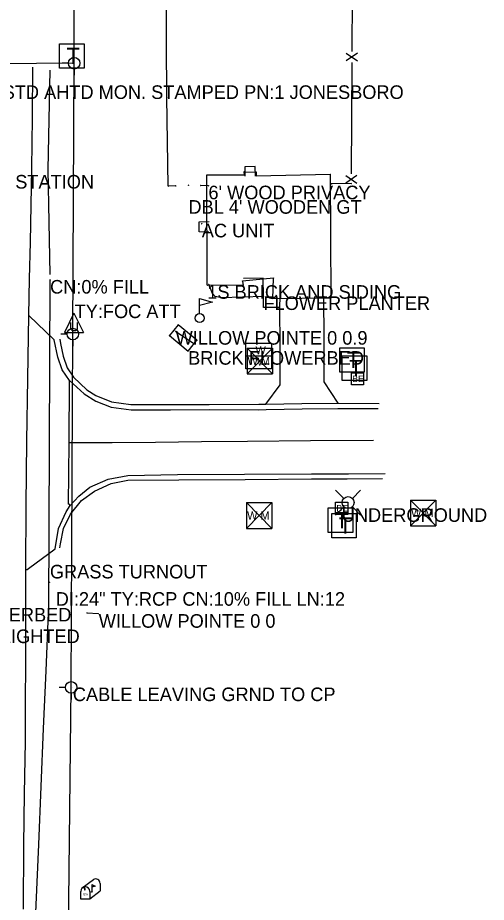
# Model space of a CAD drawing. Extents: x 1707085 to 1720058, y 548761 to 560063.
# Drawn here: x 1712493.1 to 1712665.4, y 550824.4 to 551149.9 of the extents above; entities that cross this region are included whole.
import ezdxf

# ---------------------------------------------------------------- set-up
doc = ezdxf.new("R2010")
doc.units = 0
for name, color, linetype in [('3', 7, 'Continuous'), ('R_Contours', 7, 'Continuous'), ('R_Horz Alg Annot', 7, 'Continuous'), ('R_Water Annot', 7, 'Continuous'), ('S_BUILDING', 7, 'Continuous'), ('S_BUILDING_ANNOT', 7, 'Continuous'), ('S_CURB', 7, 'Continuous'), ('S_DRG_PT_SYM', 7, 'Continuous'), ('S_DRIVEWAY', 7, 'Continuous'), ('S_EDGE_CONCRETE', 7, 'Continuous'), ('S_EDGE_PAVEMENT', 7, 'Continuous'), ('S_ELECTRIC_UTILITIES', 7, 'Continuous'), ('S_ELECTRIC_UTILITIES_ANNOT', 7, 'Continuous'), ('S_FENCE_ANNOT', 7, 'Continuous'), ('S_FLAG_POLE', 7, 'Continuous'), ('S_GATE_ANNOT', 7, 'Continuous'), ('S_MAILBOX', 7, 'Continuous'), ('S_MISC_STRUCTURES', 7, 'Continuous'), ('S_MISC_STRUCTURES_ANNOT', 7, 'Continuous'), ('S_MSC_PT_SYM', 7, 'Continuous'), ('S_PAVEMENT_CROWN', 7, 'Continuous'), ('S_PRIMARY_CTL_ANNOT', 7, 'Continuous'), ('S_SIDE_DRAIN_ANNOT', 7, 'Continuous'), ('S_SIDEWALK', 7, 'Continuous'), ('S_SIGN_ANNOT', 7, 'Continuous'), ('S_STR_PT_SYM', 7, 'Continuous'), ('S_SURVEY_TEXT_ANNOT', 7, 'Continuous'), ('S_TELEPHONE_UTILITIES', 7, 'Continuous'), ('S_UNDERGROUND_CABLE', 7, 'Continuous'), ('S_UTILITY_POLE', 7, 'Continuous'), ('S_UTILITY_POLE_ANNOT', 7, 'Continuous')]:
    doc.layers.add(name, color=color, linetype=linetype)

msp = doc.modelspace()

# ---------------------------------------------------------------- linework, layer by layer
for points in [[(1712504.99, 551055.41), (1712504.65, 551074.69), (1712504.31, 551093.97), (1712504.65, 551112.3), (1712504.99, 551130.62)], [(1712498.93, 550801.18), (1712499.86, 550823.46), (1712500.8, 550845.74), (1712501.7, 550867.04), (1712502.61, 550888.35), (1712503.52, 550909.65), (1712504.42, 550930.96)]]:
    msp.add_lwpolyline(points)
at = {"layer": '3'}
msp.add_line((1712504.5, 550932.27), (1712505, 551053.38), dxfattribs=at)
at = {"layer": 'R_Contours'}
for p, q in [((1712618.03, 551136.82), (1712613.92, 551133.97)), ((1712613.94, 551136.83), (1712618.02, 551133.95)), ((1712617.83, 551091.82), (1712613.72, 551088.97)), ((1712613.73, 551091.84), (1712617.81, 551088.95)), ((1712563.24, 551088.08), (1712560.43, 551088.11)), ((1712615.76, 551088.93), (1712608.46, 551088.73)), ((1712551.2, 551087.98), (1712548.44, 551087.93))]:
    msp.add_line(p, q, dxfattribs=at)
for points in [[(1712547.8, 551140.62), (1712547.82, 551157.97)], [(1712616.08, 551157.89), (1712615.99, 551137.44)], [(1712547.92, 551120.61), (1712547.8, 551140.62)], [(1712615.97, 551133.35), (1712615.78, 551092.44)], [(1712548.44, 551087.93), (1712547.92, 551120.61)], [(1712563.24, 551088.08), (1712560.43, 551088.11)], [(1712615.76, 551088.93), (1712608.46, 551088.73)], [(1712551.2, 551087.98), (1712548.44, 551087.93)]]:
    msp.add_lwpolyline(points, dxfattribs=at)
at = {"layer": 'R_Horz Alg Annot'}
for p, q in [((1712551.16, 551034.59), (1712557.45, 551030.23)), ((1712518.61, 550930.88), (1712522.74, 550930.71))]:
    msp.add_line(p, q, dxfattribs=at)
at = {"layer": 'R_Water Annot'}
for p, q in [((1712577, 551030.14), (1712586.42, 551030.14)), ((1712577, 551020.73), (1712577, 551030.14)), ((1712586.42, 551030.14), (1712586.42, 551020.73)), ((1712577.43, 551028.31), (1712586.77, 551028.31)), ((1712577.43, 551028.31), (1712577.43, 551018.82)), ((1712577.43, 551028.31), (1712586.77, 551018.82)), ((1712586.77, 551028.31), (1712577.43, 551018.82)), ((1712586.77, 551028.31), (1712586.77, 551018.82)), ((1712577, 551025.45), (1712586.42, 551025.45)), ((1712586.42, 551020.73), (1712577, 551020.73)), ((1712577.43, 551018.82), (1712586.77, 551018.82)), ((1712577.26, 550971.48), (1712586.6, 550971.48)), ((1712577.26, 550971.48), (1712577.26, 550961.99)), ((1712577.26, 550971.48), (1712586.6, 550961.99)), ((1712586.6, 550971.48), (1712577.26, 550961.99)), ((1712586.6, 550971.48), (1712586.6, 550961.99)), ((1712637.56, 550972.44), (1712646.9, 550972.44)), ((1712637.56, 550972.44), (1712637.56, 550962.95)), ((1712637.56, 550972.44), (1712646.9, 550962.95)), ((1712646.9, 550972.44), (1712637.56, 550962.95)), ((1712646.9, 550972.44), (1712646.9, 550962.95)), ((1712577.26, 550961.99), (1712586.6, 550961.99)), ((1712637.56, 550962.95), (1712646.9, 550962.95))]:
    msp.add_line(p, q, dxfattribs=at)
at = {"layer": 'S_BUILDING'}
for p, q in [((1712562.66, 551092.03), (1712576.47, 551092.08)), ((1712562.81, 551051.48), (1712562.66, 551092.03)), ((1712576.47, 551092.08), (1712576.36, 551093.15)), ((1712576.36, 551093.15), (1712580.78, 551093.1)), ((1712580.78, 551093.1), (1712580.79, 551091.76)), ((1712580.79, 551091.76), (1712608.03, 551092.31)), ((1712608.03, 551092.31), (1712608.25, 551046.71)), ((1712587.18, 551054.1), (1712575.82, 551052.99)), ((1712575.82, 551052.99), (1712576.02, 551051.38)), ((1712586.92, 551046.51), (1712587.18, 551054.1)), ((1712576.02, 551051.38), (1712562.81, 551051.48)), ((1712608.25, 551046.71), (1712586.92, 551046.51))]:
    msp.add_line(p, q, dxfattribs=at)
at = {"layer": 'S_CURB'}
for points in [[(1712508.53, 551031.58), (1712508.78, 551030.03), (1712509.79, 551025.42), (1712511.28, 551021.07), (1712513.66, 551017.64), (1712518.54, 551012.97), (1712521.81, 551010.85), (1712527.62, 551008.55), (1712534.69, 551007.53), (1712549.11, 551007.53), (1712563.52, 551007.52), (1712581.8, 551007.74), (1712584.38, 551007.76), (1712597.6, 551007.91), (1712610.82, 551008.05), (1712625.99, 551007.95)], [(1712508.59, 550954.87), (1712508.82, 550956.34), (1712509.94, 550961.92), (1712512.48, 550967.27), (1712516.5, 550972.32), (1712521.28, 550975.66), (1712527.45, 550978.57), (1712533.63, 550979.74), (1712552.4, 550979.84), (1712576.79, 550980.03), (1712601.19, 550980.22), (1712614.22, 550980.29), (1712627.25, 550980.35)]]:
    msp.add_lwpolyline(points, dxfattribs=at)
at = {"layer": 'S_DRG_PT_SYM'}
for points in [[(1712505, 551053.38), (1712505, 551053.43), (1712505, 551053.38), (1712504.95, 551053.38), (1712505, 551053.38), (1712505, 551053.33), (1712505, 551053.38), (1712505.05, 551053.38)], [(1712504.5, 550932.27), (1712504.5, 550932.32), (1712504.5, 550932.27), (1712504.45, 550932.27), (1712504.5, 550932.27), (1712504.5, 550932.22), (1712504.5, 550932.27), (1712504.55, 550932.27)]]:
    msp.add_lwpolyline(points, dxfattribs=at)
at = {"layer": 'S_DRIVEWAY'}
for points in [[(1712584.38, 551007.76), (1712589.64, 551014.78), (1712589.57, 551029.04), (1712589.5, 551043.3), (1712589.68, 551047.28)], [(1712605.56, 551047.42), (1712605.64, 551031.65), (1712605.73, 551015.88), (1712610.82, 551008.05)]]:
    msp.add_lwpolyline(points, dxfattribs=at)
at = {"layer": 'S_EDGE_CONCRETE'}
for points in [[(1712580.59, 551091.6), (1712580.48, 551095.15), (1712576.65, 551095.07), (1712576.68, 551091.61)], [(1712563.43, 551071), (1712559.79, 551071.16), (1712559.77, 551074.77), (1712563.47, 551074.85)], [(1712496.11, 550946.87), (1712496.59, 550946.88), (1712497, 550947.29), (1712506.81, 550954.45), (1712508.12, 550961.97), (1712510.89, 550968.09), (1712512.39, 550970.38), (1712512.06, 550970.86), (1712511.74, 550970.86), (1712511.96, 550993.46), (1712512.19, 551016.36), (1712509.5, 551020.39), (1712507.88, 551024.95), (1712506.56, 551031.37), (1712497.17, 551040.29)]]:
    msp.add_lwpolyline(points, dxfattribs=at)
at = {"layer": 'S_EDGE_PAVEMENT'}
for points in [[(1712495.22, 550821.87), (1712495.32, 550845.5), (1712495.61, 550864.5), (1712495.9, 550883.5), (1712495.97, 550897.95), (1712496.05, 550912.4), (1712496.08, 550929.64), (1712496.11, 550946.87), (1712496.25, 550970.48), (1712496.4, 550994.08), (1712496.78, 551017.19), (1712497.17, 551040.29), (1712497.46, 551053.82), (1712497.74, 551067.34), (1712498.02, 551080.87), (1712498.31, 551094.4), (1712498.48, 551113.06), (1712498.65, 551131.73)], [(1712512.19, 551016.36), (1712517.57, 551011.46), (1712521.81, 551008.85), (1712527.45, 551006.63), (1712534.78, 551005.59), (1712549.27, 551005.67), (1712563.76, 551005.74), (1712581.66, 551005.67), (1712584.49, 551005.79), (1712597.65, 551005.95), (1712610.82, 551006.1), (1712625.61, 551006.09)], [(1712512.39, 550970.38), (1712515.63, 550973.88), (1712519.67, 550977.13), (1712526.39, 550980.12), (1712533.55, 550981.46), (1712551.87, 550981.8), (1712576.52, 550981.93), (1712601.16, 550982.06), (1712614.69, 550982.13), (1712628.23, 550982.2)]]:
    msp.add_lwpolyline(points, dxfattribs=at)
at = {"layer": 'S_ELECTRIC_UTILITIES'}
for points in [[(1712615.82, 551014.78), (1712615.82, 551019.28), (1712620.32, 551019.28), (1712620.32, 551014.78)], [(1712609.99, 550967.15), (1712609.99, 550971.65), (1712614.49, 550971.65), (1712614.49, 550967.15)]]:
    msp.add_lwpolyline(points, close=True, dxfattribs=at)
at = {"layer": 'S_FLAG_POLE'}
for p, q in [((1712560, 551041), (1712560, 551046.54)), ((1712560, 551046.54), (1712564.77, 551045.26)), ((1712564.77, 551045.26), (1712560, 551043.98))]:
    msp.add_line(p, q, dxfattribs=at)
msp.add_circle((1712560, 551039.37), 1.63, dxfattribs=at)
at = {"layer": 'S_MAILBOX'}
for p, q in [((1712516.8, 550829.75), (1712520.93, 550832.86)), ((1712520.41, 550831.04), (1712520.41, 550828.33)), ((1712523.36, 550831.39), (1712523.36, 550828.67)), ((1712516.24, 550828.48), (1712516.24, 550825.76)), ((1712519.57, 550825.76), (1712523.36, 550828.67)), ((1712519.57, 550828.48), (1712519.57, 550825.76)), ((1712516.24, 550825.76), (1712519.57, 550825.76))]:
    msp.add_line(p, q, dxfattribs=at)
for points in [[(1712520.41, 550831.04), (1712521.52, 550830.38), (1712520.41, 550830.03)], [(1712517.43, 550829.59), (1712517.65, 550829.45), (1712517.65, 550829.07), (1712517.95, 550829.07), (1712517.95, 550829.43), (1712517.76, 550829.68), (1712517.43, 550829.62)]]:
    msp.add_lwpolyline(points, dxfattribs=at)
for centre, end in [((1712521.7, 550831.39), 117.5718), ((1712517.91, 550828.48), 180)]:
    msp.add_arc(centre, 1.66, 0, end, dxfattribs=at)
msp.add_ellipse((1712520.41, 550828.33), major_axis=(0.145, 0.132), ratio=0.564646, dxfattribs=at)
at = {"layer": 'S_MISC_STRUCTURES'}
for p, q in [((1712564.74, 551048.38), (1712563.37, 551051.67)), ((1712565.69, 551047.28), (1712564.74, 551048.38)), ((1712568.1, 551046.85), (1712565.69, 551047.28)), ((1712583.47, 551047.35), (1712568.1, 551046.85)), ((1712552.13, 551036.94), (1712548.88, 551033.01)), ((1712559.01, 551031.22), (1712552.13, 551036.94)), ((1712548.88, 551033.01), (1712555.78, 551027.22)), ((1712555.78, 551027.22), (1712559.01, 551031.22))]:
    msp.add_line(p, q, dxfattribs=at)
at = {"layer": 'S_MSC_PT_SYM'}
for points in [[(1712547.8, 551140.62), (1712547.8, 551140.67), (1712547.8, 551140.62), (1712547.75, 551140.62), (1712547.8, 551140.62), (1712547.8, 551140.57), (1712547.8, 551140.62), (1712547.85, 551140.62)], [(1712547.92, 551120.61), (1712547.92, 551120.66), (1712547.92, 551120.61), (1712547.87, 551120.61), (1712547.92, 551120.61), (1712547.92, 551120.56), (1712547.92, 551120.61), (1712547.97, 551120.61)], [(1712548.44, 551087.93), (1712548.44, 551087.98), (1712548.44, 551087.93), (1712548.39, 551087.93), (1712548.44, 551087.93), (1712548.44, 551087.88), (1712548.44, 551087.93), (1712548.49, 551087.93)], [(1712551.2, 551087.98), (1712551.2, 551088.03), (1712551.2, 551087.98), (1712551.15, 551087.98), (1712551.2, 551087.98), (1712551.2, 551087.93), (1712551.2, 551087.98), (1712551.25, 551087.98)], [(1712555.88, 551088.24), (1712555.88, 551088.29), (1712555.88, 551088.24), (1712555.83, 551088.24), (1712555.88, 551088.24), (1712555.88, 551088.19), (1712555.88, 551088.24), (1712555.93, 551088.24)], [(1712560.43, 551088.11), (1712560.43, 551088.16), (1712560.43, 551088.11), (1712560.38, 551088.11), (1712560.43, 551088.11), (1712560.43, 551088.06), (1712560.43, 551088.11), (1712560.48, 551088.11)], [(1712563.24, 551088.08), (1712563.24, 551088.13), (1712563.24, 551088.08), (1712563.19, 551088.08), (1712563.24, 551088.08), (1712563.24, 551088.03), (1712563.24, 551088.08), (1712563.29, 551088.08)], [(1712608.46, 551088.73), (1712608.46, 551088.78), (1712608.46, 551088.73), (1712608.41, 551088.73), (1712608.46, 551088.73), (1712608.46, 551088.68), (1712608.46, 551088.73), (1712608.51, 551088.73)], [(1712615.76, 551088.93), (1712615.76, 551088.98), (1712615.76, 551088.93), (1712615.71, 551088.93), (1712615.76, 551088.93), (1712615.76, 551088.88), (1712615.76, 551088.93), (1712615.81, 551088.93)], [(1712560.79, 551074.07), (1712560.79, 551074.12), (1712560.79, 551074.07), (1712560.74, 551074.07), (1712560.79, 551074.07), (1712560.79, 551074.02), (1712560.79, 551074.07), (1712560.84, 551074.07)], [(1712563.37, 551051.67), (1712563.37, 551051.72), (1712563.37, 551051.67), (1712563.32, 551051.67), (1712563.37, 551051.67), (1712563.37, 551051.62), (1712563.37, 551051.67), (1712563.42, 551051.67)], [(1712564.74, 551048.38), (1712564.74, 551048.43), (1712564.74, 551048.38), (1712564.69, 551048.38), (1712564.74, 551048.38), (1712564.74, 551048.33), (1712564.74, 551048.38), (1712564.79, 551048.38)], [(1712565.69, 551047.28), (1712565.69, 551047.33), (1712565.69, 551047.28), (1712565.64, 551047.28), (1712565.69, 551047.28), (1712565.69, 551047.23), (1712565.69, 551047.28), (1712565.74, 551047.28)], [(1712568.1, 551046.85), (1712568.1, 551046.9), (1712568.1, 551046.85), (1712568.05, 551046.85), (1712568.1, 551046.85), (1712568.1, 551046.8), (1712568.1, 551046.85), (1712568.15, 551046.85)], [(1712583.47, 551047.35), (1712583.47, 551047.4), (1712583.47, 551047.35), (1712583.42, 551047.35), (1712583.47, 551047.35), (1712583.47, 551047.3), (1712583.47, 551047.35), (1712583.52, 551047.35)], [(1712552.13, 551036.94), (1712552.13, 551036.99), (1712552.13, 551036.94), (1712552.08, 551036.94), (1712552.13, 551036.94), (1712552.13, 551036.89), (1712552.13, 551036.94), (1712552.18, 551036.94)], [(1712548.88, 551033.01), (1712548.88, 551033.06), (1712548.88, 551033.01), (1712548.83, 551033.01), (1712548.88, 551033.01), (1712548.88, 551032.96), (1712548.88, 551033.01), (1712548.93, 551033.01)], [(1712551.16, 551034.59), (1712551.16, 551034.64), (1712551.16, 551034.59), (1712551.11, 551034.59), (1712551.16, 551034.59), (1712551.16, 551034.54), (1712551.16, 551034.59), (1712551.21, 551034.59)], [(1712557.45, 551030.23), (1712557.45, 551030.28), (1712557.45, 551030.23), (1712557.4, 551030.23), (1712557.45, 551030.23), (1712557.45, 551030.18), (1712557.45, 551030.23), (1712557.5, 551030.23)], [(1712559.01, 551031.22), (1712559.01, 551031.27), (1712559.01, 551031.22), (1712558.96, 551031.22), (1712559.01, 551031.22), (1712559.01, 551031.17), (1712559.01, 551031.22), (1712559.06, 551031.22)], [(1712555.78, 551027.22), (1712555.78, 551027.27), (1712555.78, 551027.22), (1712555.73, 551027.22), (1712555.78, 551027.22), (1712555.78, 551027.17), (1712555.78, 551027.22), (1712555.83, 551027.22)], [(1712504.73, 550942.18), (1712504.73, 550942.23), (1712504.73, 550942.18), (1712504.68, 550942.18), (1712504.73, 550942.18), (1712504.73, 550942.13), (1712504.73, 550942.18), (1712504.78, 550942.18)], [(1712518.61, 550930.88), (1712518.61, 550930.93), (1712518.61, 550930.88), (1712518.56, 550930.88), (1712518.61, 550930.88), (1712518.61, 550930.83), (1712518.61, 550930.88), (1712518.66, 550930.88)], [(1712522.74, 550930.71), (1712522.74, 550930.76), (1712522.74, 550930.71), (1712522.69, 550930.71), (1712522.74, 550930.71), (1712522.74, 550930.66), (1712522.74, 550930.71), (1712522.79, 550930.71)], [(1712513.37, 550903.46), (1712513.37, 550903.51), (1712513.37, 550903.46), (1712513.32, 550903.46), (1712513.37, 550903.46), (1712513.37, 550903.41), (1712513.37, 550903.46), (1712513.42, 550903.46)]]:
    msp.add_lwpolyline(points, dxfattribs=at)
at = {"layer": 'S_PAVEMENT_CROWN'}
msp.add_lwpolyline([(1712623.93, 550994.3), (1712600.74, 550994.16), (1712577.55, 550994.02), (1712560.66, 550993.8), (1712543.77, 550993.59), (1712527.87, 550993.52), (1712511.96, 550993.46)], dxfattribs=at)
at = {"layer": 'S_SIDEWALK'}
msp.add_lwpolyline([(1712589.5, 551043.3), (1712583.45, 551043.28), (1712583.47, 551047.35), (1712583.41, 551054.03), (1712576.11, 551053.95)], dxfattribs=at)
at = {"layer": 'S_STR_PT_SYM'}
for points in [[(1712562.66, 551092.03), (1712562.66, 551092.08), (1712562.66, 551092.03), (1712562.61, 551092.03), (1712562.66, 551092.03), (1712562.66, 551091.98), (1712562.66, 551092.03), (1712562.71, 551092.03)], [(1712576.36, 551093.15), (1712576.36, 551093.2), (1712576.36, 551093.15), (1712576.31, 551093.15), (1712576.36, 551093.15), (1712576.36, 551093.1), (1712576.36, 551093.15), (1712576.41, 551093.15)], [(1712576.47, 551092.08), (1712576.47, 551092.13), (1712576.47, 551092.08), (1712576.42, 551092.08), (1712576.47, 551092.08), (1712576.47, 551092.03), (1712576.47, 551092.08), (1712576.52, 551092.08)], [(1712580.78, 551093.1), (1712580.78, 551093.15), (1712580.78, 551093.1), (1712580.73, 551093.1), (1712580.78, 551093.1), (1712580.78, 551093.05), (1712580.78, 551093.1), (1712580.83, 551093.1)], [(1712580.79, 551091.76), (1712580.79, 551091.81), (1712580.79, 551091.76), (1712580.74, 551091.76), (1712580.79, 551091.76), (1712580.79, 551091.71), (1712580.79, 551091.76), (1712580.84, 551091.76)], [(1712608.03, 551092.31), (1712608.03, 551092.36), (1712608.03, 551092.31), (1712607.98, 551092.31), (1712608.03, 551092.31), (1712608.03, 551092.26), (1712608.03, 551092.31), (1712608.08, 551092.31)], [(1712575.82, 551052.99), (1712575.82, 551053.04), (1712575.82, 551052.99), (1712575.77, 551052.99), (1712575.82, 551052.99), (1712575.82, 551052.94), (1712575.82, 551052.99), (1712575.87, 551052.99)], [(1712587.18, 551054.1), (1712587.18, 551054.15), (1712587.18, 551054.1), (1712587.13, 551054.1), (1712587.18, 551054.1), (1712587.18, 551054.05), (1712587.18, 551054.1), (1712587.23, 551054.1)], [(1712562.81, 551051.48), (1712562.81, 551051.53), (1712562.81, 551051.48), (1712562.76, 551051.48), (1712562.81, 551051.48), (1712562.81, 551051.43), (1712562.81, 551051.48), (1712562.86, 551051.48)], [(1712576.02, 551051.38), (1712576.02, 551051.43), (1712576.02, 551051.38), (1712575.97, 551051.38), (1712576.02, 551051.38), (1712576.02, 551051.33), (1712576.02, 551051.38), (1712576.07, 551051.38)], [(1712586.92, 551046.51), (1712586.92, 551046.56), (1712586.92, 551046.51), (1712586.87, 551046.51), (1712586.92, 551046.51), (1712586.92, 551046.46), (1712586.92, 551046.51), (1712586.97, 551046.51)], [(1712608.25, 551046.71), (1712608.25, 551046.76), (1712608.25, 551046.71), (1712608.2, 551046.71), (1712608.25, 551046.71), (1712608.25, 551046.66), (1712608.25, 551046.71), (1712608.3, 551046.71)]]:
    msp.add_lwpolyline(points, dxfattribs=at)
at = {"layer": 'S_TELEPHONE_UTILITIES'}
for points in [[(1712508.51, 551131.3), (1712508.51, 551140.3), (1712517.51, 551140.3), (1712517.51, 551131.3)], [(1712611.56, 551019.46), (1712611.56, 551028.46), (1712620.56, 551028.46), (1712620.56, 551019.46)], [(1712612.48, 551016.45), (1712612.48, 551025.45), (1712621.48, 551025.45), (1712621.48, 551016.45)], [(1712607.3, 550960.52), (1712607.3, 550969.52), (1712616.3, 550969.52), (1712616.3, 550960.52)], [(1712608.6, 550958.52), (1712608.6, 550967.52), (1712617.6, 550967.52), (1712617.6, 550958.52)]]:
    msp.add_lwpolyline(points, close=True, dxfattribs=at)
at = {"layer": 'S_UNDERGROUND_CABLE'}
for p, q in [((1712513.77, 551041.2), (1712510.25, 551034.11)), ((1712513.77, 551041.2), (1712517.26, 551034.11)), ((1712512.57, 551035.35), (1712512.57, 551037.79)), ((1712514.94, 551037.79), (1712514.94, 551035.35)), ((1712510.25, 551034.11), (1712517.26, 551034.11)), ((1712513.19, 551034.69), (1712512.57, 551035.35)), ((1712514.39, 551034.69), (1712513.19, 551034.69)), ((1712514.94, 551035.35), (1712514.39, 551034.69))]:
    msp.add_line(p, q, dxfattribs=at)
at = {"layer": 'S_UTILITY_POLE'}
for p, q in [((1712513.87, 551133.13), (1712513.87, 551316)), ((1712513.87, 551135.24), (1712513.87, 551137.48)), ((1712511.78, 551133.11), (1712509.45, 551133.11)), ((1712513.95, 551128.69), (1712513.95, 551131.01)), ((1712513.37, 551035.6), (1712513.37, 551037.84)), ((1712511.28, 551033.46), (1712508.95, 551033.46)), ((1712513.45, 551029.05), (1712513.45, 551031.37)), ((1712613.01, 550973.06), (1712610.03, 550976.05)), ((1712616.19, 550973.06), (1712619.17, 550976.05)), ((1712613.01, 550969.88), (1712610.03, 550966.9)), ((1712616.19, 550969.88), (1712619.17, 550966.9)), ((1712512.75, 550905.64), (1712512.75, 550907.88)), ((1712510.66, 550903.5), (1712508.34, 550903.5)), ((1712512.83, 550899.09), (1712512.83, 550901.41))]:
    msp.add_line(p, q, dxfattribs=at)
msp.add_lwpolyline([(1712497.7, 549518.48), (1712500.91, 549949.57), (1712500.58, 550149.34), (1712502.49, 550416.34), (1712509.79, 550634.49), (1712512.76, 550903.53), (1712513.37, 551033.49), (1712513.87, 551133.13), (1712444.45, 551132.54)], dxfattribs=at)
for centre, radius in [((1712513.87, 551133.13), 2.13), ((1712513.37, 551033.49), 2.13), ((1712614.61, 550971.48), 2.21), ((1712512.76, 550903.53), 2.13)]:
    msp.add_circle(centre, radius, dxfattribs=at)

# ---------------------------------------------------------------- texts
at = {"layer": 'R_Water Annot'}
for s, p in [('W', (1712580.55, 551025.98)), ('W M', (1712577.64, 551022.08)), ('V', (1712580.79, 551021.92)), ('W M', (1712577.47, 550965.25)), ('W M', (1712637.76, 550966.21))]:
    msp.add_text(s, height=3, rotation=360, dxfattribs=at).set_placement(p)
at = {"layer": 'S_BUILDING_ANNOT'}
msp.add_text('1S BRICK AND SIDING', height=5, dxfattribs=at).set_placement((1712562.81, 551046.48))
at = {"layer": 'S_ELECTRIC_UTILITIES'}
for p in [(1712616.14, 551015.83), (1712610.31, 550968.2)]:
    msp.add_text('BE', height=2.4, rotation=360, dxfattribs=at).set_placement(p)
at = {"layer": 'S_ELECTRIC_UTILITIES_ANNOT'}
msp.add_text('UNDERGROUND', height=5, dxfattribs=at).set_placement((1712612.26, 550964.4))
at = {"layer": 'S_FENCE_ANNOT'}
msp.add_text("6' WOOD PRIVACY", height=5, dxfattribs=at).set_placement((1712563.24, 551083.08))
at = {"layer": 'S_GATE_ANNOT'}
msp.add_text("DBL 4' WOODEN GT", height=5, dxfattribs=at).set_placement((1712555.88, 551077.76))
at = {"layer": 'S_MAILBOX'}
msp.add_text('US', height=0.96, rotation=360, dxfattribs=at).set_placement((1712517.01, 550826.96))
at = {"layer": 'S_MISC_STRUCTURES_ANNOT'}
for s, p in [('GAS TEST STATION', (1712457.27, 551087.02)), ('AC UNIT', (1712560.79, 551069.07)), ('FLOWER PLANTER', (1712583.47, 551042.35)), ('BRICK FLOWERBED', (1712555.78, 551022.22)), ("3.6'X3.6' BRICK FLOWERBED", (1712420.74, 550927.76))]:
    msp.add_text(s, height=5, dxfattribs=at).set_placement(p)
at = {"layer": 'S_PRIMARY_CTL_ANNOT'}
msp.add_text('PD:STD AHTD MON. STAMPED PN:1 JONESBORO', height=5, dxfattribs=at).set_placement((1712476.42, 551119.99))
at = {"layer": 'S_SIDE_DRAIN_ANNOT'}
for s, p in [('CN:0% FILL', (1712505, 551048.38)), ('DI:24" TY:RCP CN:10% FILL LN:12', (1712507.06, 550933.55))]:
    msp.add_text(s, height=5, dxfattribs=at).set_placement(p)
at = {"layer": 'S_SIGN_ANNOT'}
for s, p in [('WILLOW POINTE 0 0.9', (1712551.16, 551029.59)), ('WILLOW POINTE 0 0', (1712522.88, 550925.45)), ("CHANGEABLE 0 4' TY:PLST,MTL,LIGHTED", (1712382.73, 550919.81))]:
    msp.add_text(s, height=5, dxfattribs=at).set_placement(p)
at = {"layer": 'S_SURVEY_TEXT_ANNOT'}
for s, p in [('GRASS TURNOUT', (1712504.94, 550943.59)), ('CABLE LEAVING GRND TO CP', (1712513.37, 550898.46))]:
    msp.add_text(s, height=5, dxfattribs=at).set_placement(p)
at = {"layer": 'S_TELEPHONE_UTILITIES'}
for p in [(1712511.07, 551132.8), (1712614.13, 551020.96), (1712615.05, 551017.95), (1712609.86, 550962.02), (1712611.16, 550960.02)]:
    msp.add_text('T', height=6, rotation=360, dxfattribs=at).set_placement(p)
at = {"layer": 'S_UTILITY_POLE_ANNOT'}
msp.add_text('TY:FOC ATT', height=5, dxfattribs=at).set_placement((1712514.02, 551039.36))

doc.saveas('drawing.dxf')
